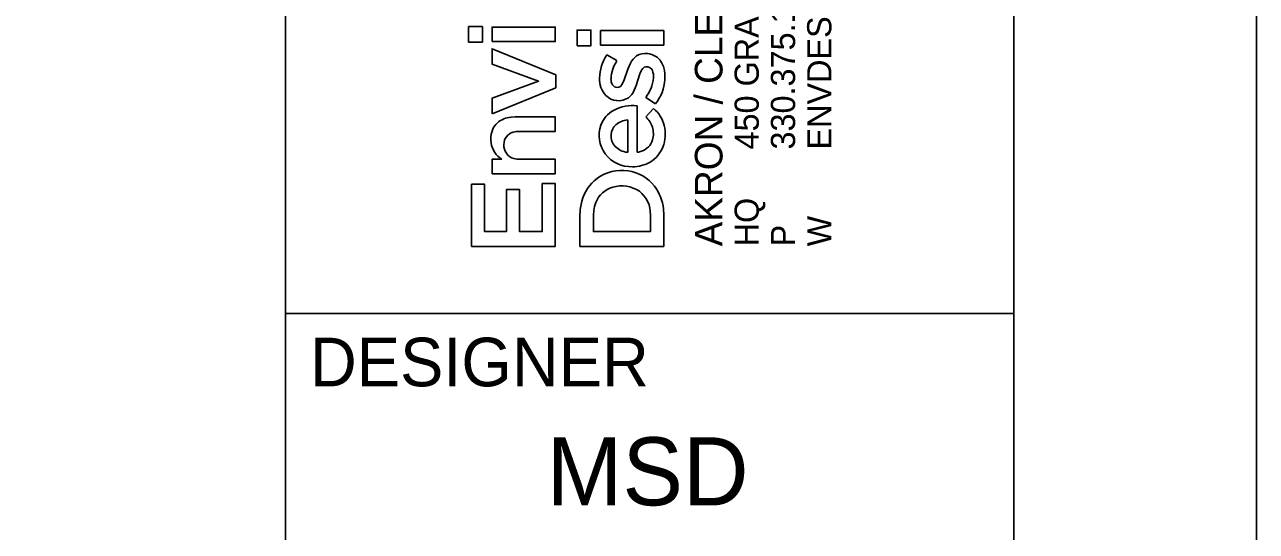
# Model space of a CAD drawing. Extents: x -6.6 to 34, y -1.6 to 22.
# Drawn here: x 31.462 to 34, y 2.552 to 3.594 of the extents above; entities that cross this region are included whole.
import ezdxf

# ---------------------------------------------------------------- set-up
doc = ezdxf.new("R2010")
doc.units = 0
for name, color, linetype in [('SH_Border', 7, 'Continuous'), ('SH_Cut_Line', 7, 'Continuous'), ('SH_Data', 7, 'Continuous')]:
    doc.layers.add(name, color=color, linetype=linetype)

msp = doc.modelspace()

# ---------------------------------------------------------------- linework, layer by layer
at = {"layer": 'SH_Border'}
for p, q in [((32, 0.5), (32, 21.5)), ((32, 3), (33.5, 3))]:
    msp.add_line(p, q, dxfattribs=at)
msp.add_lwpolyline([(1.5, 21.5), (33.5, 21.5), (33.5, 0.5), (1.5, 0.5)], close=True, dxfattribs=at)
at = {"layer": 'SH_Cut_Line'}
msp.add_lwpolyline([(0, 0), (34, 0), (34, 22), (0, 22)], close=True, dxfattribs=at)
at = {"layer": 'SH_Data'}
for p, q in [((32.3771, 3.5582), (32.3771, 3.5903)), ((32.3771, 3.5903), (32.4054, 3.5903)), ((32.4054, 3.5903), (32.4054, 3.5582)), ((32.4254, 3.5594), (32.4254, 3.5893)), ((32.4254, 3.5893), (32.5557, 3.5893)), ((32.5557, 3.5893), (32.5557, 3.5594)), ((32.6005, 3.5511), (32.6005, 3.5832)), ((32.6005, 3.5832), (32.6289, 3.5832)), ((32.6289, 3.5832), (32.6289, 3.5511)), ((32.6489, 3.5523), (32.6489, 3.5822)), ((32.6489, 3.5822), (32.7792, 3.5822)), ((32.7792, 3.5822), (32.7792, 3.5523)), ((32.4054, 3.5582), (32.3771, 3.5582)), ((32.5557, 3.5594), (32.4254, 3.5594)), ((32.4254, 3.5133), (32.4254, 3.5446)), ((32.4254, 3.5446), (32.5567, 3.4913)), ((32.6289, 3.5511), (32.6005, 3.5511)), ((32.7792, 3.5523), (32.6489, 3.5523)), ((32.6615, 3.5321), (32.6827, 3.5203)), ((32.5212, 3.478), (32.4254, 3.5133)), ((32.6967, 3.4787), (32.7048, 3.5026)), ((32.7048, 3.5026), (32.7104, 3.5153)), ((32.4254, 3.4429), (32.5212, 3.478)), ((32.5567, 3.4913), (32.5567, 3.4644)), ((32.693, 3.4712), (32.6967, 3.4787)), ((32.7298, 3.4933), (32.7221, 3.4688)), ((32.7334, 3.501), (32.7298, 3.4933)), ((32.5567, 3.4644), (32.4254, 3.4109)), ((32.7221, 3.4688), (32.7182, 3.4592)), ((32.4254, 3.4109), (32.4254, 3.4429)), ((32.7245, 3.4275), (32.7246, 3.3319)), ((32.7621, 3.4314), (32.742, 3.4447)), ((32.4644, 3.404), (32.4729, 3.4044)), ((32.4729, 3.4044), (32.5557, 3.4044)), ((32.5557, 3.4044), (32.5557, 3.3746)), ((32.7423, 3.4046), (32.7577, 3.422)), ((32.7049, 3.3318), (32.7049, 3.3983)), ((32.5557, 3.3746), (32.4814, 3.3746)), ((32.7036, 3.3317), (32.7049, 3.3318)), ((32.4254, 3.2875), (32.4254, 3.3173)), ((32.4254, 3.3173), (32.4455, 3.3173)), ((32.4822, 3.3173), (32.5557, 3.3173)), ((32.5557, 3.3173), (32.5557, 3.2876)), ((32.5557, 3.2876), (32.4254, 3.2875)), ((32.383, 3.1379), (32.383, 3.266)), ((32.383, 3.266), (32.4101, 3.266)), ((32.4101, 3.266), (32.4101, 3.1683)), ((32.455, 3.1683), (32.455, 3.2549)), ((32.455, 3.2549), (32.4822, 3.2549)), ((32.4822, 3.2549), (32.4822, 3.1683)), ((32.5286, 3.1683), (32.5286, 3.2672)), ((32.5286, 3.2672), (32.5557, 3.2672)), ((32.5557, 3.2672), (32.5557, 3.1379)), ((32.6064, 3.138), (32.6064, 3.204)), ((32.6347, 3.2118), (32.6341, 3.2023)), ((32.6341, 3.2023), (32.6341, 3.1684)), ((32.7515, 3.1683), (32.7515, 3.2024)), ((32.7785, 3.215), (32.7792, 3.2021)), ((32.7792, 3.2021), (32.7792, 3.138)), ((32.4101, 3.1683), (32.455, 3.1683)), ((32.4822, 3.1683), (32.5286, 3.1683)), ((32.6341, 3.1684), (32.7515, 3.1683)), ((32.5557, 3.1379), (32.383, 3.1379)), ((32.7792, 3.138), (32.6064, 3.138))]:
    msp.add_line(p, q, dxfattribs=at)
for points in [[(32.3771, 3.5582), (32.3771, 3.5903), (32.4054, 3.5903), (32.4054, 3.5582)], [(32.4254, 3.5594), (32.4254, 3.5893), (32.5557, 3.5893), (32.5557, 3.5594)], [(32.6005, 3.5511), (32.6005, 3.5832), (32.6289, 3.5832), (32.6289, 3.5511)], [(32.6489, 3.5523), (32.6489, 3.5822), (32.7792, 3.5822), (32.7792, 3.5523)], [(32.4254, 3.4109), (32.4254, 3.4429), (32.5212, 3.478), (32.4254, 3.5133), (32.4254, 3.5446), (32.5567, 3.4913), (32.5567, 3.4644)], [(32.383, 3.1379), (32.383, 3.266), (32.4101, 3.266), (32.4101, 3.1683), (32.455, 3.1683), (32.455, 3.2549), (32.4822, 3.2549), (32.4822, 3.1683), (32.5286, 3.1683), (32.5286, 3.2672), (32.5557, 3.2672), (32.5557, 3.1379)]]:
    msp.add_lwpolyline(points, close=True, dxfattribs=at)
for points in [[(32.6615, 3.5321), (32.6827, 3.5203)], [(32.693, 3.4712), (32.6967, 3.4787), (32.7048, 3.5026), (32.7104, 3.5153)], [(32.7334, 3.501), (32.7298, 3.4933), (32.7221, 3.4688), (32.7182, 3.4592)], [(32.7245, 3.4275), (32.7246, 3.3319)], [(32.7621, 3.4314), (32.742, 3.4447)], [(32.4644, 3.404), (32.4729, 3.4044), (32.5557, 3.4044), (32.5557, 3.3746), (32.4814, 3.3746)], [(32.7423, 3.4046), (32.7577, 3.422)], [(32.7036, 3.3317), (32.7049, 3.3318), (32.7049, 3.3983)], [(32.4254, 3.2875), (32.4254, 3.3173), (32.4455, 3.3173)], [(32.4822, 3.3173), (32.5557, 3.3173), (32.5557, 3.2876), (32.4254, 3.2875)], [(32.7785, 3.215), (32.7792, 3.2021), (32.7792, 3.138), (32.6064, 3.138)], [(32.6064, 3.138), (32.6064, 3.204)], [(32.6347, 3.2118), (32.6341, 3.2023), (32.6341, 3.1684), (32.7515, 3.1683), (32.7515, 3.2024)]]:
    msp.add_lwpolyline(points, dxfattribs=at)
for centre, radius, start, end in [((32.7364, 3.4826), 0.0897, 146.531, 178.7571), ((32.7364, 3.4826), 0.0897, 146.531, 178.7571), ((32.7466, 3.4971), 0.0405, 125.5118, 153.4159), ((32.7466, 3.4971), 0.0405, 125.5118, 153.4159), ((32.7406, 3.5026), 0.0326, 80.1719, 122.5197), ((32.7406, 3.5026), 0.0326, 80.1719, 122.5197), ((32.7428, 3.4982), 0.0367, 47.7934, 84.6892), ((32.7428, 3.4982), 0.0367, 47.7934, 84.6892), ((32.7452, 3.4789), 0.0749, 146.5112, 176.9101), ((32.7452, 3.4789), 0.0749, 146.5112, 176.9101), ((32.7438, 3.4963), 0.0114, 76.6609, 155.7053), ((32.7438, 3.4963), 0.0114, 76.6609, 155.7053), ((32.744, 3.4951), 0.0126, 21.5098, 78.5262), ((32.744, 3.4951), 0.0126, 21.5098, 78.5262), ((32.7379, 3.4946), 0.0427, 14.9966, 46.2063), ((32.7379, 3.4946), 0.0427, 14.9966, 46.2063), ((32.7104, 3.4867), 0.0712, 355.8306, 15.3914), ((32.7104, 3.4867), 0.0712, 355.8306, 15.3914), ((32.6967, 3.4824), 0.0501, 177.5366, 222.7932), ((32.6967, 3.4824), 0.0501, 177.5366, 222.7932), ((32.6931, 3.4823), 0.0228, 178.4747, 211.0868), ((32.6931, 3.4823), 0.0228, 178.4747, 211.0868), ((32.6825, 3.4915), 0.0757, 321.811, 354.7969), ((32.6825, 3.4915), 0.0757, 321.811, 354.7969), ((32.7259, 3.4877), 0.0321, 354.5726, 22.068), ((32.7259, 3.4877), 0.0321, 354.5726, 22.068), ((32.6895, 3.4882), 0.0922, 321.9777, 355.8738), ((32.6895, 3.4882), 0.0922, 321.9777, 355.8738), ((32.6833, 3.4767), 0.0115, 212.2368, 268.3777), ((32.6833, 3.4767), 0.0115, 212.2368, 268.3777), ((32.6834, 3.4759), 0.0107, 267.716, 333.7337), ((32.6834, 3.4759), 0.0107, 267.716, 333.7337), ((32.681, 3.4758), 0.0408, 308.0877, 335.9874), ((32.681, 3.4758), 0.0408, 308.0877, 335.9874), ((32.686, 3.4753), 0.0375, 225.9854, 302.4797), ((32.686, 3.4753), 0.0375, 225.9854, 302.4797), ((32.7152, 3.3441), 0.0838, 83.615, 118.2876), ((32.7152, 3.3441), 0.0838, 83.615, 118.2876), ((32.4687, 3.3543), 0.0499, 94.9696, 130.2225), ((32.4687, 3.3543), 0.0499, 94.9696, 130.2225), ((32.7024, 3.3691), 0.0558, 118.8308, 160.6244), ((32.7024, 3.3691), 0.0558, 118.8308, 160.6244), ((32.7038, 3.3656), 0.0549, 19.0357, 45.4406), ((32.7038, 3.3656), 0.0549, 19.0357, 45.4406), ((32.7174, 3.3717), 0.0644, 13.5336, 51.3615), ((32.7174, 3.3717), 0.0644, 13.5336, 51.3615), ((32.4787, 3.3582), 0.056, 162.2736, 187.7919), ((32.4787, 3.3582), 0.056, 162.2736, 187.7919), ((32.4635, 3.3626), 0.0402, 132.2219, 161.6818), ((32.4635, 3.3626), 0.0402, 132.2219, 161.6818), ((32.7104, 3.3661), 0.0644, 160.5201, 215.7831), ((32.7104, 3.3661), 0.0644, 160.5201, 215.7831), ((32.7005, 3.3663), 0.0298, 132.9851, 177.179), ((32.7005, 3.3663), 0.0298, 132.9851, 177.179), ((32.7079, 3.3561), 0.0424, 94.008, 130.8817), ((32.7079, 3.3561), 0.0424, 94.008, 130.8817), ((32.7107, 3.3697), 0.047, 344.6059, 17.007), ((32.7107, 3.3697), 0.047, 344.6059, 17.007), ((32.7064, 3.3692), 0.0758, 339.3542, 13.3785), ((32.7064, 3.3692), 0.0758, 339.3542, 13.3785), ((32.4703, 3.358), 0.0476, 188.962, 238.7037), ((32.4703, 3.358), 0.0476, 188.962, 238.7037), ((32.4748, 3.3487), 0.025, 103.6865, 182.2187), ((32.4748, 3.3487), 0.025, 103.6865, 182.2187), ((32.4811, 3.3286), 0.046, 89.6049, 105.3284), ((32.4811, 3.3286), 0.046, 89.6049, 105.3284), ((32.7017, 3.365), 0.0311, 175.0013, 223.283), ((32.7017, 3.365), 0.0311, 175.0013, 223.283), ((32.7224, 3.3671), 0.035, 288.0077, 343.5508), ((32.7224, 3.3671), 0.035, 288.0077, 343.5508), ((32.4773, 3.3456), 0.0276, 175.5854, 255.1439), ((32.4773, 3.3456), 0.0276, 175.5854, 255.1439), ((32.7125, 3.3705), 0.0687, 217.7452, 271.6543), ((32.7125, 3.3705), 0.0687, 217.7452, 271.6543), ((32.7089, 3.3736), 0.0423, 225.0619, 262.7974), ((32.7089, 3.3736), 0.0423, 225.0619, 262.7974), ((32.7247, 3.3522), 0.0202, 269.7003, 294.8711), ((32.7247, 3.3522), 0.0202, 269.7003, 294.8711), ((32.7189, 3.3652), 0.0626, 300.9427, 338.7323), ((32.7189, 3.3652), 0.0626, 300.9427, 338.7323), ((32.4818, 3.3595), 0.0422, 254.0916, 270.5284), ((32.4818, 3.3595), 0.0422, 254.0916, 270.5284), ((32.7155, 3.3724), 0.0706, 269.2048, 300.3341), ((32.7155, 3.3724), 0.0706, 269.2048, 300.3341), ((32.6939, 3.2089), 0.0865, 127.2362, 165.148), ((32.6939, 3.2089), 0.0865, 127.2362, 165.148), ((32.6923, 3.2079), 0.0864, 81.194, 125.9984), ((32.6923, 3.2079), 0.0864, 81.194, 125.9984), ((32.6946, 3.2113), 0.0827, 37.8521, 82.402), ((32.6946, 3.2113), 0.0827, 37.8521, 82.402), ((32.6889, 3.2078), 0.054, 106.1881, 157.3861), ((32.6889, 3.2078), 0.054, 106.1881, 157.3861), ((32.6928, 3.1986), 0.0639, 55.6727, 107.2093), ((32.6928, 3.1986), 0.0639, 55.6727, 107.2093), ((32.6929, 3.205), 0.0587, 357.4662, 52.2665), ((32.6929, 3.205), 0.0587, 357.4662, 52.2665), ((32.6859, 3.2057), 0.0931, 5.7333, 37.304), ((32.6859, 3.2057), 0.0931, 5.7333, 37.304), ((32.7143, 3.2028), 0.1078, 164.7861, 179.3704), ((32.7143, 3.2028), 0.1078, 164.7861, 179.3704), ((32.6983, 3.2039), 0.0641, 157.3571, 172.9275), ((32.6983, 3.2039), 0.0641, 157.3571, 172.9275)]:
    msp.add_arc(centre, radius, start, end, dxfattribs=at)

# ---------------------------------------------------------------- texts
for s, height, p in [('450 GRANT ST., AKRON, OH  44311', 0.049846, (32.9749, 3.3374)), ('AKRON / CLEVELAND / COLUMBUS', 0.056969, (32.9001, 3.138)), ('ENVDESIGNGROUP.COM', 0.049846, (33.1244, 3.3374)), ('330.375.1390', 0.049846, (33.0497, 3.3374)), ('HQ ', 0.04985, (32.9749, 3.138)), ('W', 0.0498, (33.1244, 3.138)), ('P', 0.0498, (33.0497, 3.138))]:
    msp.add_text(s, height=height, rotation=90, dxfattribs=at).set_placement(p)
for s, height, p in [('DESIGNER', 0.1, (32.05, 2.85)), ('MSD', 0.14, (32.5379, 2.605))]:
    msp.add_text(s, height=height, dxfattribs=at).set_placement(p)

doc.saveas('drawing.dxf')
